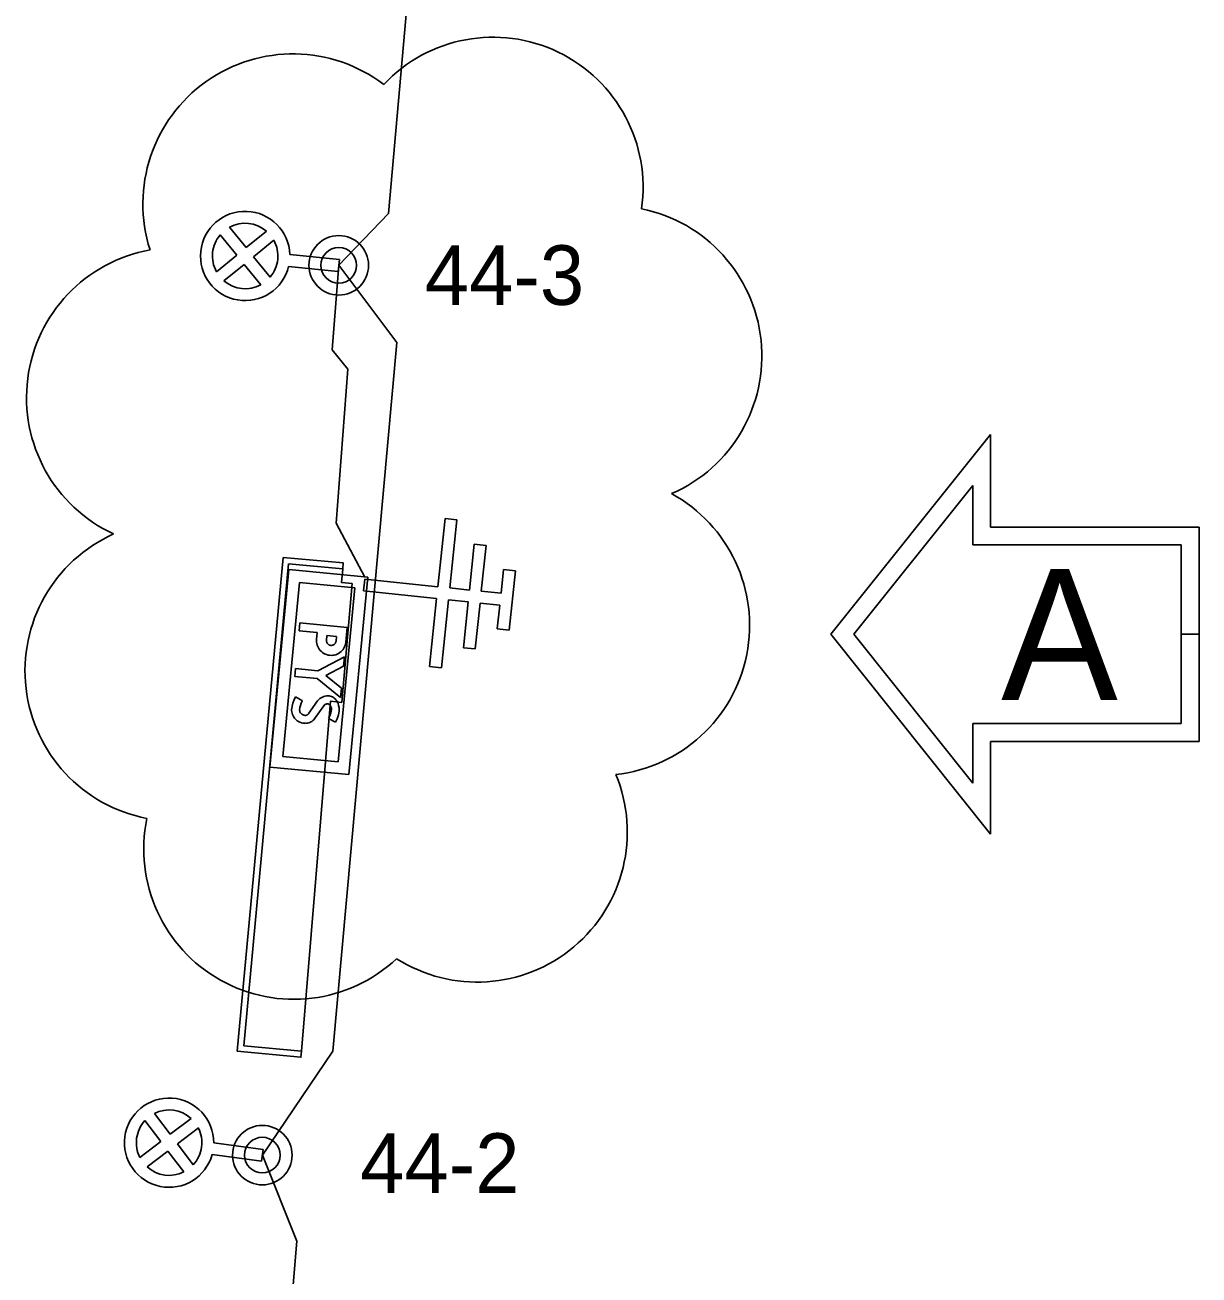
# Model space of a CAD drawing. Extents: x 25497851 to 25498523, y 6686544 to 6687372.
# Drawn here: x 25498238.3 to 25498297.4, y 6687053.4 to 6687116.4 of the extents above; entities that cross this region are included whole.
import ezdxf

# ---------------------------------------------------------------- set-up
doc = ezdxf.new("R2010")
doc.units = 0
for name, color, linetype in [('AP_Rajapinta', 7, 'Continuous'), ('AP_Reunakivi', 7, 'Continuous'), ('KAAPELI', 7, 'Continuous'), ('KEYGWT_ANNOTATION', 7, 'Continuous'), ('MUU_SUUNNITELMAVIIVA', 7, 'Continuous'), ('MUU_UV-SUUNNITELMASYMBOLI', 7, 'Continuous'), ('PYLVAS', 7, 'Continuous'), ('VALAISIN', 7, 'Continuous')]:
    doc.layers.add(name, color=color, linetype=linetype)

msp = doc.modelspace()

# ---------------------------------------------------------------- linework, layer by layer
at = {"layer": 'AP_Rajapinta'}
for p, q in [((25498249.282, 6687064.992), (25498251.535, 6687089.288)), ((25498251.535, 6687089.288), (25498254.273, 6687089.032)), ((25498254.749, 6687088.289), (25498254.234, 6687082.306)), ((25498249.282, 6687064.992), (25498252.195, 6687064.727))]:
    msp.add_line(p, q, dxfattribs=at)
for points in [[(25498251.264, 6687089.614), (25498254.301, 6687089.333), (25498254.273, 6687089.032)], [(25498254.273, 6687089.032), (25498254.215, 6687088.339), (25498254.749, 6687088.289)], [(25498252.195, 6687064.727), (25498253.651, 6687082.36), (25498254.234, 6687082.306)], [(25498248.955, 6687064.721), (25498252.169, 6687064.423), (25498252.195, 6687064.727)]]:
    msp.add_lwpolyline(points, dxfattribs=at)
at = {"layer": 'AP_Reunakivi'}
msp.add_line((25498248.955, 6687064.721), (25498251.264, 6687089.614), dxfattribs=at)
at = {"layer": 'KAAPELI'}
for points in [[(25498258.332, 6687154.238), (25498260.462, 6687150.684), (25498256.587, 6687106.941), (25498254.072, 6687104.332)], [(25498254.072, 6687104.332), (25498257.002, 6687100.447), (25498253.772, 6687064.73), (25498250.221, 6687059.486)], [(25498254.072, 6687104.332), (25498253.744, 6687100.074), (25498254.537, 6687099.101), (25498253.946, 6687091.338), (25498255.39, 6687088.619)], [(25498250.221, 6687059.486), (25498251.962, 6687055.149), (25498248.636, 6687015.334), (25498246.085, 6687011.72)]]:
    msp.add_lwpolyline(points, dxfattribs=at)
at = {"layer": 'MUU_SUUNNITELMAVIIVA'}
for centre, radius, start, end in [((25498261.848, 6687108.266), 7.563, 351.75001, 136.75001), ((25498251.766, 6687107.421), 7.566, 52.81195, 197.81195), ((25498267.827, 6687099.764), 7.569, 293.52322, 78.52322), ((25498245.902, 6687097.66), 7.566, 100.19156, 245.19156), ((25498267.211, 6687086.189), 7.566, 276.2706, 61.2706), ((25498245.827, 6687083.89), 7.567, 114.17828, 259.17828), ((25498261.049, 6687075.77), 7.565, 237.52831, 22.52831), ((25498251.812, 6687074.906), 7.566, 168.16852, 313.16852)]:
    msp.add_arc(centre, radius, start, end, dxfattribs=at)
at = {"layer": 'MUU_UV-SUUNNITELMASYMBOLI'}
for p, q in [((25498286.927, 6687095.803), (25498278.874, 6687085.737)), ((25498286.927, 6687091.137), (25498286.927, 6687095.803)), ((25498280.027, 6687085.737), (25498286.027, 6687093.237)), ((25498286.027, 6687093.237), (25498286.027, 6687090.237)), ((25498259.069, 6687088.134), (25498259.428, 6687091.565)), ((25498259.428, 6687091.565), (25498260.025, 6687091.503)), ((25498260.025, 6687091.503), (25498259.666, 6687088.071)), ((25498297.427, 6687091.137), (25498286.927, 6687091.137)), ((25498297.427, 6687085.737), (25498297.427, 6687091.137)), ((25498260.66, 6687087.967), (25498260.902, 6687090.28)), ((25498260.902, 6687090.28), (25498261.499, 6687090.217)), ((25498261.499, 6687090.217), (25498261.257, 6687087.905)), ((25498286.027, 6687090.237), (25498296.527, 6687090.237)), ((25498296.527, 6687090.237), (25498296.527, 6687085.737)), ((25498250.606, 6687079.04), (25498251.551, 6687088.995)), ((25498251.551, 6687088.995), (25498255.534, 6687088.617)), ((25498262.251, 6687087.801), (25498262.376, 6687088.994)), ((25498262.376, 6687088.994), (25498262.973, 6687088.932)), ((25498262.973, 6687088.932), (25498262.661, 6687085.948)), ((25498251.26, 6687079.581), (25498252.092, 6687088.341)), ((25498252.092, 6687088.341), (25498254.88, 6687088.077)), ((25498255.534, 6687088.617), (25498254.588, 6687078.662)), ((25498255.327, 6687087.922), (25498255.389, 6687088.519)), ((25498255.389, 6687088.519), (25498259.069, 6687088.134)), ((25498254.88, 6687088.077), (25498254.047, 6687079.316)), ((25498259.006, 6687087.537), (25498255.327, 6687087.922)), ((25498259.666, 6687088.071), (25498260.66, 6687087.967)), ((25498261.257, 6687087.905), (25498262.251, 6687087.801)), ((25498258.647, 6687084.106), (25498259.006, 6687087.537)), ((25498259.603, 6687087.475), (25498259.244, 6687084.043)), ((25498260.598, 6687087.371), (25498259.603, 6687087.475)), ((25498260.356, 6687085.058), (25498260.598, 6687087.371)), ((25498261.194, 6687087.308), (25498260.952, 6687084.996)), ((25498262.189, 6687087.204), (25498261.194, 6687087.308)), ((25498262.064, 6687086.011), (25498262.189, 6687087.204)), ((25498252.075, 6687085.912), (25498252.113, 6687086.311)), ((25498262.661, 6687085.948), (25498262.064, 6687086.011)), ((25498253.472, 6687085.679), (25498253.956, 6687085.633)), ((25498253.956, 6687085.633), (25498253.934, 6687085.397)), ((25498278.874, 6687085.737), (25498286.927, 6687075.671)), ((25498286.027, 6687078.237), (25498280.027, 6687085.737)), ((25498297.427, 6687085.737), (25498296.527, 6687085.737)), ((25498296.527, 6687085.737), (25498296.527, 6687081.237)), ((25498297.427, 6687080.337), (25498297.427, 6687085.737)), ((25498254.361, 6687084.608), (25498254.316, 6687084.131)), ((25498260.952, 6687084.996), (25498260.356, 6687085.058)), ((25498251.857, 6687083.608), (25498251.894, 6687084.006)), ((25498259.244, 6687084.043), (25498258.647, 6687084.106)), ((25498253.512, 6687082.635), (25498253.545, 6687082.631)), ((25498254.211, 6687083.029), (25498254.166, 6687082.553)), ((25498251.893, 6687082.582), (25498252.237, 6687082.378)), ((25498252.999, 6687082.376), (25498253.019, 6687082.401)), ((25498253.323, 6687082.14), (25498253.313, 6687082.128)), ((25498253.642, 6687082.171), (25498253.541, 6687082.236)), ((25498253.642, 6687082.171), (25498253.541, 6687082.236)), ((25498253.704, 6687082.004), (25498253.642, 6687082.171)), ((25498253.704, 6687082.004), (25498253.642, 6687082.171)), ((25498253.708, 6687081.948), (25498253.704, 6687082.004)), ((25498253.708, 6687081.948), (25498253.704, 6687082.004)), ((25498253.974, 6687082.367), (25498253.995, 6687082.342)), ((25498251.699, 6687081.955), (25498251.708, 6687081.977)), ((25498251.93, 6687081.418), (25498251.922, 6687081.424)), ((25498252.102, 6687081.908), (25498252.104, 6687081.876)), ((25498252.175, 6687081.736), (25498252.188, 6687081.724)), ((25498252.369, 6687081.65), (25498252.384, 6687081.649)), ((25498252.546, 6687081.73), (25498252.56, 6687081.754)), ((25498252.887, 6687081.523), (25498252.894, 6687081.532)), ((25498253.913, 6687081.3), (25498253.562, 6687081.494)), ((25498254.099, 6687081.916), (25498254.099, 6687081.864)), ((25498252.394, 6687081.249), (25498252.379, 6687081.248)), ((25498296.527, 6687081.237), (25498286.027, 6687081.237)), ((25498286.027, 6687081.237), (25498286.027, 6687078.237)), ((25498286.927, 6687075.671), (25498286.927, 6687080.337)), ((25498286.927, 6687080.337), (25498297.427, 6687080.337)), ((25498254.047, 6687079.316), (25498251.26, 6687079.581)), ((25498254.588, 6687078.662), (25498250.606, 6687079.04))]:
    msp.add_line(p, q, dxfattribs=at)
for points in [[(25498252.984, 6687085.826), (25498252.075, 6687085.912)], [(25498252.113, 6687086.311), (25498254.501, 6687086.084), (25498254.43, 6687085.336)], [(25498252.95, 6687085.476), (25498252.984, 6687085.826)], [(25498254.428, 6687085.323), (25498254.418, 6687085.257), (25498254.397, 6687085.181), (25498254.369, 6687085.109), (25498254.333, 6687085.041), (25498254.291, 6687084.976), (25498254.242, 6687084.916), (25498254.187, 6687084.861), (25498254.126, 6687084.813), (25498254.061, 6687084.771), (25498253.991, 6687084.736), (25498253.919, 6687084.709), (25498253.844, 6687084.689), (25498253.767, 6687084.678), (25498253.69, 6687084.674), (25498253.612, 6687084.678), (25498253.536, 6687084.691), (25498253.461, 6687084.712), (25498253.389, 6687084.74), (25498253.32, 6687084.775), (25498253.255, 6687084.818), (25498253.195, 6687084.867), (25498253.141, 6687084.922), (25498253.092, 6687084.983), (25498253.05, 6687085.048), (25498253.016, 6687085.118), (25498252.988, 6687085.19), (25498252.968, 6687085.265), (25498252.957, 6687085.341), (25498252.953, 6687085.417), (25498252.95, 6687085.476)], [(25498253.448, 6687085.429), (25498253.472, 6687085.679)], [(25498253.934, 6687085.397), (25498253.928, 6687085.363), (25498253.922, 6687085.339), (25498253.913, 6687085.316), (25498253.901, 6687085.293), (25498253.887, 6687085.273), (25498253.871, 6687085.253), (25498253.854, 6687085.235), (25498253.834, 6687085.22), (25498253.813, 6687085.206), (25498253.79, 6687085.195), (25498253.766, 6687085.186), (25498253.743, 6687085.18), (25498253.718, 6687085.176), (25498253.692, 6687085.175), (25498253.667, 6687085.176), (25498253.643, 6687085.18), (25498253.619, 6687085.187), (25498253.595, 6687085.196), (25498253.573, 6687085.207), (25498253.552, 6687085.221), (25498253.532, 6687085.238), (25498253.515, 6687085.255), (25498253.499, 6687085.275), (25498253.486, 6687085.296), (25498253.474, 6687085.318), (25498253.465, 6687085.342), (25498253.459, 6687085.366), (25498253.454, 6687085.391), (25498253.45, 6687085.414), (25498253.448, 6687085.429)], [(25498251.894, 6687084.006), (25498253.021, 6687083.899), (25498254.361, 6687084.608)], [(25498254.318, 6687084.132), (25498253.424, 6687083.66)], [(25498252.983, 6687083.501), (25498251.857, 6687083.608)], [(25498254.166, 6687082.553), (25498252.983, 6687083.501)], [(25498253.424, 6687083.66), (25498254.211, 6687083.029)], [(25498253.019, 6687082.401), (25498253.063, 6687082.446), (25498253.119, 6687082.493), (25498253.181, 6687082.535), (25498253.247, 6687082.57), (25498253.316, 6687082.598), (25498253.387, 6687082.618), (25498253.459, 6687082.631), (25498253.512, 6687082.635)], [(25498253.019, 6687082.401), (25498253.063, 6687082.446), (25498253.119, 6687082.493), (25498253.181, 6687082.535), (25498253.247, 6687082.57), (25498253.316, 6687082.598), (25498253.387, 6687082.618), (25498253.459, 6687082.631), (25498253.512, 6687082.635)], [(25498253.545, 6687082.631), (25498253.591, 6687082.627), (25498253.647, 6687082.616), (25498253.7, 6687082.599), (25498253.751, 6687082.577), (25498253.801, 6687082.549), (25498253.846, 6687082.516), (25498253.888, 6687082.479), (25498253.925, 6687082.438), (25498253.958, 6687082.394), (25498253.974, 6687082.367)], [(25498253.545, 6687082.631), (25498253.591, 6687082.627), (25498253.647, 6687082.616), (25498253.7, 6687082.599), (25498253.751, 6687082.577), (25498253.801, 6687082.549), (25498253.846, 6687082.516), (25498253.888, 6687082.479), (25498253.925, 6687082.438), (25498253.958, 6687082.394), (25498253.974, 6687082.367)], [(25498251.708, 6687081.977), (25498251.724, 6687082.108), (25498251.757, 6687082.258), (25498251.806, 6687082.404), (25498251.87, 6687082.545), (25498251.893, 6687082.582)], [(25498251.708, 6687081.977), (25498251.724, 6687082.108), (25498251.757, 6687082.258), (25498251.806, 6687082.404), (25498251.87, 6687082.545), (25498251.893, 6687082.582)], [(25498252.237, 6687082.378), (25498252.225, 6687082.359), (25498252.179, 6687082.257), (25498252.143, 6687082.151), (25498252.118, 6687082.041), (25498252.102, 6687081.908)], [(25498252.237, 6687082.378), (25498252.225, 6687082.359), (25498252.179, 6687082.257), (25498252.143, 6687082.151), (25498252.118, 6687082.041), (25498252.102, 6687081.908)], [(25498252.56, 6687081.754), (25498252.999, 6687082.376)], [(25498252.56, 6687081.754), (25498252.999, 6687082.376)], [(25498253.313, 6687082.128), (25498252.887, 6687081.523)], [(25498253.313, 6687082.128), (25498252.887, 6687081.523)], [(25498253.541, 6687082.236), (25498253.509, 6687082.233), (25498253.476, 6687082.228), (25498253.445, 6687082.219), (25498253.415, 6687082.207), (25498253.387, 6687082.192), (25498253.361, 6687082.174), (25498253.336, 6687082.153), (25498253.323, 6687082.14)], [(25498253.541, 6687082.236), (25498253.509, 6687082.233), (25498253.476, 6687082.228), (25498253.445, 6687082.219), (25498253.415, 6687082.207), (25498253.387, 6687082.192), (25498253.361, 6687082.174), (25498253.336, 6687082.153), (25498253.323, 6687082.14)], [(25498253.995, 6687082.342), (25498254.035, 6687082.248), (25498254.068, 6687082.14), (25498254.089, 6687082.03), (25498254.098, 6687081.925), (25498254.099, 6687081.916)], [(25498253.995, 6687082.342), (25498254.035, 6687082.248), (25498254.068, 6687082.14), (25498254.089, 6687082.03), (25498254.098, 6687081.925), (25498254.099, 6687081.916)], [(25498251.922, 6687081.424), (25498251.893, 6687081.452), (25498251.847, 6687081.503), (25498251.806, 6687081.56), (25498251.771, 6687081.622), (25498251.742, 6687081.687), (25498251.72, 6687081.755), (25498251.706, 6687081.824), (25498251.699, 6687081.895), (25498251.699, 6687081.955)], [(25498251.922, 6687081.424), (25498251.893, 6687081.452), (25498251.847, 6687081.503), (25498251.806, 6687081.56), (25498251.771, 6687081.622), (25498251.742, 6687081.687), (25498251.72, 6687081.755), (25498251.706, 6687081.824), (25498251.699, 6687081.895), (25498251.699, 6687081.955)], [(25498252.379, 6687081.248), (25498252.338, 6687081.25), (25498252.264, 6687081.26), (25498252.189, 6687081.278), (25498252.118, 6687081.304), (25498252.049, 6687081.337), (25498251.983, 6687081.377), (25498251.93, 6687081.418)], [(25498252.379, 6687081.248), (25498252.338, 6687081.25), (25498252.264, 6687081.26), (25498252.189, 6687081.278), (25498252.118, 6687081.304), (25498252.049, 6687081.337), (25498251.983, 6687081.377), (25498251.93, 6687081.418)], [(25498252.104, 6687081.876), (25498252.108, 6687081.856), (25498252.117, 6687081.829), (25498252.128, 6687081.802), (25498252.142, 6687081.777), (25498252.16, 6687081.754), (25498252.175, 6687081.736)], [(25498252.104, 6687081.876), (25498252.108, 6687081.856), (25498252.117, 6687081.829), (25498252.128, 6687081.802), (25498252.142, 6687081.777), (25498252.16, 6687081.754), (25498252.175, 6687081.736)], [(25498252.188, 6687081.724), (25498252.211, 6687081.707), (25498252.24, 6687081.689), (25498252.271, 6687081.674), (25498252.304, 6687081.662), (25498252.338, 6687081.654), (25498252.369, 6687081.65)], [(25498252.188, 6687081.724), (25498252.211, 6687081.707), (25498252.24, 6687081.689), (25498252.271, 6687081.674), (25498252.304, 6687081.662), (25498252.338, 6687081.654), (25498252.369, 6687081.65)], [(25498252.384, 6687081.649), (25498252.413, 6687081.65), (25498252.431, 6687081.652), (25498252.448, 6687081.656), (25498252.466, 6687081.662), (25498252.482, 6687081.67), (25498252.497, 6687081.679), (25498252.512, 6687081.69), (25498252.525, 6687081.703), (25498252.537, 6687081.716), (25498252.546, 6687081.73)], [(25498252.384, 6687081.649), (25498252.413, 6687081.65), (25498252.431, 6687081.652), (25498252.448, 6687081.656), (25498252.466, 6687081.662), (25498252.482, 6687081.67), (25498252.497, 6687081.679), (25498252.512, 6687081.69), (25498252.525, 6687081.703), (25498252.537, 6687081.716), (25498252.546, 6687081.73)], [(25498252.894, 6687081.532), (25498252.887, 6687081.519), (25498252.854, 6687081.472), (25498252.815, 6687081.426), (25498252.771, 6687081.385), (25498252.724, 6687081.348), (25498252.672, 6687081.317), (25498252.618, 6687081.292), (25498252.561, 6687081.272), (25498252.502, 6687081.258), (25498252.443, 6687081.25), (25498252.394, 6687081.249)], [(25498252.894, 6687081.532), (25498252.887, 6687081.519), (25498252.854, 6687081.472), (25498252.815, 6687081.426), (25498252.771, 6687081.385), (25498252.724, 6687081.348), (25498252.672, 6687081.317), (25498252.618, 6687081.292), (25498252.561, 6687081.272), (25498252.502, 6687081.258), (25498252.443, 6687081.25), (25498252.394, 6687081.249)], [(25498253.562, 6687081.494), (25498253.622, 6687081.628), (25498253.672, 6687081.781), (25498253.708, 6687081.948)], [(25498253.562, 6687081.494), (25498253.622, 6687081.628), (25498253.672, 6687081.781), (25498253.708, 6687081.948)], [(25498254.099, 6687081.864), (25498254.059, 6687081.676), (25498253.995, 6687081.483), (25498253.913, 6687081.3)], [(25498254.099, 6687081.864), (25498254.059, 6687081.676), (25498253.995, 6687081.483), (25498253.913, 6687081.3)]]:
    msp.add_lwpolyline(points, dxfattribs=at)
at = {"layer": 'PYLVAS'}
for centre, radius in [((25498254.072, 6687104.332), 1.5), ((25498254.072, 6687104.332), 0.9), ((25498250.221, 6687059.486), 1.5), ((25498250.221, 6687059.486), 0.9)]:
    msp.add_circle(centre, radius, dxfattribs=at)
at = {"layer": 'VALAISIN'}
for p, q in [((25498249.399, 6687105.225), (25498248.564, 6687106.25)), ((25498250.424, 6687106.06), (25498249.399, 6687105.225)), ((25498248.098, 6687105.871), (25498248.934, 6687104.846)), ((25498249.778, 6687104.76), (25498250.803, 6687105.595)), ((25498248.934, 6687104.846), (25498247.908, 6687104.011)), ((25498250.613, 6687103.734), (25498249.778, 6687104.76)), ((25498251.605, 6687104.875), (25498254.102, 6687104.619)), ((25498248.287, 6687103.545), (25498249.313, 6687104.381)), ((25498249.313, 6687104.381), (25498250.148, 6687103.355)), ((25498254.041, 6687104.023), (25498251.544, 6687104.278)), ((25498254.102, 6687104.619), (25498254.041, 6687104.023)), ((25498244.302, 6687061.224), (25498245.102, 6687060.171)), ((25498245.58, 6687060.535), (25498244.779, 6687061.587)), ((25498246.632, 6687061.335), (25498245.58, 6687060.535)), ((25498245.943, 6687060.057), (25498246.996, 6687060.857)), ((25498245.102, 6687060.171), (25498244.049, 6687059.371)), ((25498246.743, 6687059.004), (25498245.943, 6687060.057)), ((25498247.772, 6687060.111), (25498250.26, 6687059.772)), ((25498244.413, 6687058.893), (25498245.465, 6687059.694)), ((25498245.465, 6687059.694), (25498246.266, 6687058.641)), ((25498250.179, 6687059.178), (25498247.692, 6687059.516)), ((25498250.26, 6687059.772), (25498250.179, 6687059.178))]:
    msp.add_line(p, q, dxfattribs=at)
for centre, radius, start, end in [((25498249.356, 6687104.803), 2.25, 1.82875, 174.16649), ((25498249.356, 6687104.803), 1.65, 49.64217, 118.69081), ((25498249.356, 6687104.803), 1.65, 139.64217, 174.16649), ((25498249.356, 6687104.803), 1.65, 354.16649, 28.69081), ((25498249.356, 6687104.803), 2.25, 174.16649, 346.50424), ((25498249.356, 6687104.803), 1.65, 174.16649, 208.69081), ((25498249.356, 6687104.803), 1.65, 319.64217, 354.16649), ((25498249.356, 6687104.803), 1.65, 229.64217, 298.69081), ((25498245.522, 6687060.114), 2.25, 359.91149, 172.24923), ((25498245.522, 6687060.114), 1.65, 137.72492, 172.24923), ((25498245.522, 6687060.114), 1.65, 47.72492, 116.77355), ((25498245.522, 6687060.114), 1.65, 352.24923, 26.77355), ((25498245.522, 6687060.114), 2.25, 172.24923, 344.58698), ((25498245.522, 6687060.114), 1.65, 172.24923, 206.77355), ((25498245.522, 6687060.114), 1.65, 317.72492, 352.24923), ((25498245.522, 6687060.114), 1.65, 227.72492, 296.77355)]:
    msp.add_arc(centre, radius, start, end, dxfattribs=at)

# ---------------------------------------------------------------- texts
at = {"layer": 'KEYGWT_ANNOTATION'}
for s, p in [('44-3', (25498258.411, 6687102.339)), ('44-2', (25498255.151, 6687057.585))]:
    msp.add_text(s, height=3, dxfattribs=at).set_placement(p)
at = {"layer": 'MUU_UV-SUUNNITELMASYMBOLI'}
msp.add_text('A', height=6.6, dxfattribs=at).set_placement((25498287.451, 6687082.419))

doc.saveas('drawing.dxf')
